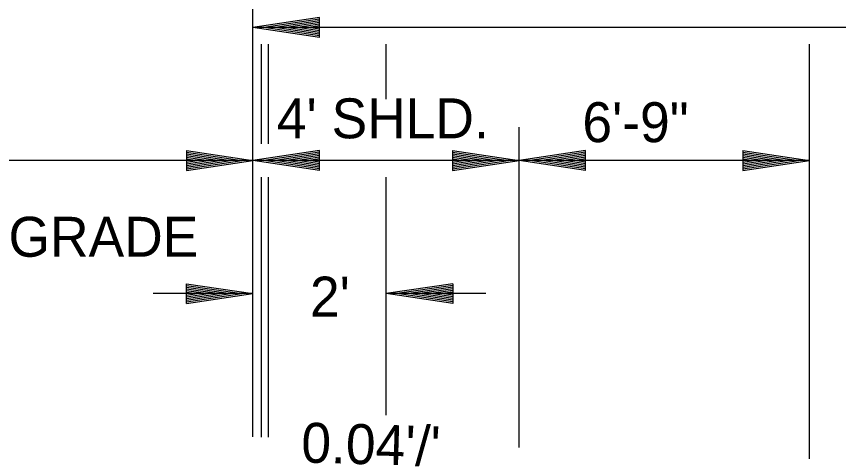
# Model space of a CAD drawing. Extents: x 138 to 3619, y -519 to 1449.
# Drawn here: x 685.7 to 809.3, y 541.7 to 607.1 of the extents above; entities that cross this region are included whole.
import ezdxf

# ---------------------------------------------------------------- set-up
doc = ezdxf.new("R2010")
doc.units = 0
doc.layers.add('R_Annotation', color=7, linetype='Continuous')
doc.layers.add('R_Dimension', color=7, linetype='Continuous')

msp = doc.modelspace()

# ---------------------------------------------------------------- linework, layer by layer
at = {"layer": 'R_Dimension'}
for p, q in [((721.26, 585.39), (721.26, 610.39)), ((731.26, 606.89), (721.26, 605.39)), ((731.26, 603.89), (731.26, 606.89)), ((731.26, 606.64), (722.93, 605.39)), ((731.26, 606.39), (724.65, 605.39)), ((731.26, 606.14), (726.32, 605.39)), ((731.26, 605.88), (728.01, 605.39)), ((731.26, 605.63), (729.68, 605.39)), ((843.66, 605.39), (721.26, 605.39)), ((731.26, 603.89), (721.26, 605.39)), ((731.26, 604.14), (722.93, 605.39)), ((731.26, 604.4), (724.65, 605.39)), ((731.26, 604.65), (726.32, 605.39)), ((731.26, 604.91), (728.01, 605.39)), ((731.26, 605.16), (729.68, 605.39)), ((722.53, 587.89), (722.53, 602.89)), ((723.58, 587.89), (723.58, 602.89)), ((741.28, 594.6), (741.28, 602.89)), ((804.9, 533.32), (804.9, 602.89)), ((761.26, 542.26), (761.26, 590.39)), ((711.26, 586.89), (721.26, 585.39)), ((711.26, 586.89), (711.26, 583.89)), ((711.26, 586.64), (719.59, 585.39)), ((711.26, 586.39), (717.87, 585.39)), ((711.26, 586.14), (716.21, 585.39)), ((711.26, 585.88), (714.51, 585.39)), ((731.26, 586.89), (721.26, 585.39)), ((731.26, 586.64), (722.93, 585.39)), ((731.26, 586.39), (724.65, 585.39)), ((731.26, 586.14), (726.32, 585.39)), ((731.26, 585.88), (728.01, 585.39)), ((731.26, 583.89), (731.26, 586.89)), ((751.26, 586.89), (761.26, 585.39)), ((751.26, 586.89), (751.26, 583.89)), ((751.26, 586.64), (759.59, 585.39)), ((751.26, 586.39), (757.87, 585.39)), ((751.26, 586.14), (756.21, 585.39)), ((751.26, 585.88), (754.51, 585.39)), ((771.26, 586.89), (761.26, 585.39)), ((771.26, 586.64), (762.93, 585.39)), ((771.26, 586.39), (764.65, 585.39)), ((771.26, 586.14), (766.32, 585.39)), ((771.26, 585.88), (768.01, 585.39)), ((771.26, 583.89), (771.26, 586.89)), ((794.9, 586.89), (804.9, 585.39)), ((794.9, 586.89), (794.9, 583.89)), ((794.9, 586.64), (803.23, 585.39)), ((794.9, 586.39), (801.51, 585.39)), ((794.9, 586.14), (799.84, 585.39)), ((794.9, 585.88), (798.15, 585.39)), ((804.9, 585.39), (417.63, 585.39)), ((711.26, 585.63), (712.84, 585.39)), ((711.26, 583.89), (721.26, 585.39)), ((711.26, 584.9), (714.51, 585.39)), ((711.26, 584.4), (717.87, 585.39)), ((711.26, 584.14), (719.59, 585.39)), ((711.26, 584.65), (716.21, 585.39)), ((711.26, 585.16), (712.84, 585.39)), ((721.26, 543.86), (721.26, 585.39)), ((731.26, 583.89), (721.26, 585.39)), ((731.26, 584.14), (722.93, 585.39)), ((731.26, 584.4), (724.65, 585.39)), ((731.26, 584.65), (726.32, 585.39)), ((731.26, 584.91), (728.01, 585.39)), ((731.26, 585.63), (729.68, 585.39)), ((731.26, 585.16), (729.68, 585.39)), ((751.26, 585.63), (752.84, 585.39)), ((751.26, 583.89), (761.26, 585.39)), ((751.26, 584.9), (754.51, 585.39)), ((751.26, 584.4), (757.87, 585.39)), ((751.26, 584.14), (759.59, 585.39)), ((751.26, 584.65), (756.21, 585.39)), ((751.26, 585.16), (752.84, 585.39)), ((771.26, 583.89), (761.26, 585.39)), ((771.26, 584.14), (762.93, 585.39)), ((771.26, 584.4), (764.65, 585.39)), ((771.26, 584.65), (766.32, 585.39)), ((771.26, 584.91), (768.01, 585.39)), ((771.26, 585.63), (769.68, 585.39)), ((771.26, 585.16), (769.68, 585.39)), ((794.9, 585.63), (796.48, 585.39)), ((794.9, 583.89), (804.9, 585.39)), ((794.9, 584.9), (798.15, 585.39)), ((794.9, 584.4), (801.51, 585.39)), ((794.9, 584.14), (803.23, 585.39)), ((794.9, 584.65), (799.84, 585.39)), ((794.9, 585.16), (796.48, 585.39)), ((722.53, 543.8), (722.53, 582.89)), ((723.58, 543.8), (723.58, 582.89)), ((741.28, 547.13), (741.28, 582.89)), ((711.26, 566.89), (721.26, 565.39)), ((711.26, 563.89), (711.26, 566.89)), ((711.26, 566.64), (719.59, 565.39)), ((711.26, 566.39), (717.87, 565.39)), ((711.26, 566.14), (716.21, 565.39)), ((751.28, 566.89), (741.28, 565.39)), ((751.28, 566.64), (742.95, 565.39)), ((751.28, 566.39), (744.67, 565.39)), ((751.28, 566.14), (746.34, 565.39)), ((751.28, 566.89), (751.28, 563.89)), ((721.26, 565.39), (706.26, 565.39)), ((711.26, 565.88), (714.51, 565.39)), ((711.26, 565.63), (712.84, 565.39)), ((711.26, 563.89), (721.26, 565.39)), ((711.26, 564.91), (714.51, 565.39)), ((711.26, 564.4), (717.87, 565.39)), ((711.26, 564.14), (719.59, 565.39)), ((711.26, 564.65), (716.21, 565.39)), ((711.26, 565.16), (712.84, 565.39)), ((751.28, 563.89), (741.28, 565.39)), ((756.28, 565.39), (741.28, 565.39)), ((751.28, 564.14), (742.95, 565.39)), ((751.28, 564.4), (744.67, 565.39)), ((751.28, 564.65), (746.34, 565.39)), ((751.28, 565.88), (748.03, 565.39)), ((751.28, 564.9), (748.03, 565.39)), ((751.28, 565.63), (749.7, 565.39)), ((751.28, 565.16), (749.7, 565.39))]:
    msp.add_line(p, q, dxfattribs=at)

# ---------------------------------------------------------------- texts
at = {"layer": 'R_Annotation'}
for s, p in [("4' SHLD.", (724.85, 588.74)), ('6\'-9"', (770.77, 588.16)), ('PROFILE GRADE', (647.96, 570.94)), ("2'", (729.83, 561.95))]:
    msp.add_text(s, height=6, dxfattribs=at).set_placement(p)
msp.add_text("0.04'/'", height=6, rotation=358.3978, dxfattribs=at).set_placement((728.46, 540.03))

doc.saveas('drawing.dxf')
